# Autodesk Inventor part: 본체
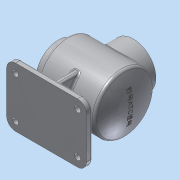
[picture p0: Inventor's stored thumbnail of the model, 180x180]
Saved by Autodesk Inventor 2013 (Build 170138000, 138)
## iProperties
Created: 2016-09
Part Number: 본체
Material: 알루미늄 6061
Document SubType Name: Modeling
Designer: dgall
Density: 2.71 g/cm^3
Mass: 972.437 g
Surface Area: 1283.14 cm^2
Volume: 358.833 cm^3
Author: dgall
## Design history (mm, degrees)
sketch "스케치1"
  geometry: L1 (-62, 0)-(60, 0); L2 (-62, 27)-(-47, 27); L3 (-47, 27)-(-47, 47); L4 (-47, 47)-(46.661, 47); L5 (-62, 27)-(-62, 38); L6 (-62, 38)-(-50, 38); L7 (-50, 38)-(-50, 50); L8 (-50, 50)-(48.562, 50); A1 r 115 centre (-55, 0) between (60, 0) and (48.562, 50); A2 r 112 centre (-55, 0) between (57, 0) and (46.661, 47); 2 further points
  constraints: 16 end point, 4 parallel, 4 point on circle, 3 perpendicular, 2 centre point, 2 point on line, 1 horizontal, 1 horizontal alignment, 1 midpoint
  dimensions: "d0" = 122 distance of L1.start L1.end; "d2" = 62 distance of L1.start point (0, 0); "d3" = 15 distance of L2.start L2.end; "d4" = 12 distance of L5.end L6.end; "d5" = 110 distance from line of L7 L1.end; "d6" = 76 diameter of L6 L1; "d7" = 54 diameter of L2 L1; "d8" = 100 diameter of L8 L1; "d9" = 94 diameter of L4 L1; "d10" = 230 diameter of A1; "d11" = 3 radial gap between concentric circles of A1 A2
revolve "회전1" sketch "스케치1" stored, may be unused: angle "d12" = 90 deg
sketch "스케치2" dims "d13" = 65
  geometry: C1 r 38 at (0, 0) reference; C2 r 27 at (0, 0) reference; 2 further points
  constraints: 2 vertical alignment, 1 coincident, 2 other
hole "구멍1" sketch "스케치2" at (0, 32.5) diameter "d15" = 3.242; stored, may be unused: countersink angle "d19" = 82 deg, drill point angle "d21" = 118 deg; dims "d16" = 8, "d17" = 3.023, "d18" = 2, "d20" = 10
node "작업 평면1"
sketch "스케치3" dims "d28" = 65
  geometry: C1 r 38 at (0, 0); C2 r 27 at (0, 0); 2 further points
  constraints: 2 centre point, 2 vertical alignment, 1 coincident, 2 other
  dimensions: "d26" = 76 diameter of C1; "d29" = 54 diameter of C2
extrude "돌출1" join sketch "스케치3" stored distance "d30" = 10; taper "d31" = 0 deg
extrude "돌출2" cut sketch "스케치3" distance "d32" = 61.5; taper "d33" = 0 deg
hole "구멍2" sketch "스케치3" diameter "d34" = 3.242; stored, may be unused: countersink angle "d38" = 82 deg, drill point angle "d40" = 118 deg; dims "d35" = 8, "d36" = 3.023, "d37" = 2, "d39" = 10
fillet "모깎기1" dims "d44" = 2
node "작업 평면2"
sketch "스케치4"
  geometry: L1 (67.5, 50)-(-67.5, 50); L2 (-67.5, 50)-(-67.5, -50); L3 (-67.5, -50)-(67.5, -50); L4 (67.5, -50)-(67.5, 50); 3 further points
  constraints: 8 end point, 2 midpoint, 2 parallel, 1 horizontal, 1 horizontal alignment, 1 perpendicular, 1 vertical alignment
  dimensions: "d46" = 135 distance of L2.end L3.end; "d48" = 100 distance of L3.end L1.start
extrude "돌출3" join sketch "스케치4" distance "d49" = 10; taper "d50" = 0 deg
fillet "모깎기2" dims "d51" = 15, "d52" = 5, "d53" = 3
sketch "스케치5"
  geometry: C1 r 5 at (-52.5, 35); C2 r 5 at (-52.5, -35); C3 r 5 at (52.5, -35); C4 r 5 at (52.5, 35); A1 r 15 centre (52.5, 35) between (67.5, 35) and (52.5, 50) reference; A2 r 15 centre (-52.5, 35) between (-52.5, 50) and (-67.5, 35) reference; A3 r 15 centre (-52.5, -35) between (-67.5, -35) and (-52.5, -50) reference; A4 r 15 centre (52.5, -35) between (52.5, -50) and (67.5, -35) reference; 1 further point
  constraints: 4 centre point, 4 coincident, 3 equal radius
  dimensions: "d54" = 10 diameter of C2
extrude "돌출4" cut sketch "스케치5" distance "d56" = 47.25; taper "d57" = 0 deg
sketch "스케치6"
  geometry: L1 (-72, 40)-(-72, 30) reference; L2 (-72, -30)-(-72, -40) reference; L3 (-72, 40)-(-72, 30) reference; L4 (-72, -30)-(-72, -40) reference; L5 (-72, -50)-(-72, -35) reference; L6 (-72, -35)-(-72, -50) reference; L7 (-72, -35)-(-72, 35) reference; L8 (-72, 50)-(-72, 35) reference; L9 (-72, 35)-(-72, 50) reference; L10 (-72, 35)-(-72, -35) reference; L11 (-30, 40)-(-72, 40); L12 (-30, -40)-(-72, -40); L13 (-72, 40)-(-72, -40); A1 r 50 centre (0, 0) between (-30, 40) and (-30, -40) reference; A2 r 50 centre (0, 0) between (-30, 40) and (-30, -40); 1 further point
  constraints: 6 end point, 4 point on circle, 3 perpendicular, 2 point on line, 1 centre point, 1 coincident, 1 concentric, 1 parallel
  dimensions: "d58" = 40 distance from line of point (0, 0) L12
extrude "돌출5" join sketch "스케치6" stored distance "d59" = 10; taper "d60" = 0 deg
sketch "스케치7"
  geometry: L1 (-45, -50)-(45.374, -50) reference; L2 (52.5, -72)-(-52.5, -72) reference; L3 (52.5, -72)-(67.5, -72) reference; L4 (67.5, -72)-(67.5, -82) reference; L5 (67.5, -82)-(52.5, -82) reference; L6 (52.5, -82)-(52.5, -72) reference; L7 (-67.5, -72)-(-52.5, -72) reference; L8 (-52.5, -72)-(-52.5, -82) reference; L9 (-52.5, -82)-(-67.5, -82) reference; L10 (-67.5, -82)-(-67.5, -72) reference; L11 (-40, -72)-(-37.988, -49); L12 (-37.988, -49)-(37.988, -49); L13 (37.988, -49)-(40, -72); L14 (-40, -72)-(40, -72); 3 further points
  constraints: 8 end point, 2 midpoint, 2 point on line, 2 vertical alignment, 1 equal length, 1 parallel, 1 perpendicular
  dimensions: "d61" = 95 deg angle of L3 L13; "d62" = 40 distance of L13.end point (0, -72); "d64" = 23 distance between parallel lines of L14 L12
extrude "돌출6" join sketch "스케치7" stored distance "d65" = 10; taper "d66" = 0 deg
fillet "모깎기3" dims "d67" = 3
fillet "모깎기4" dims "d68" = 3
chamfer "모따기1" distance "d69" = 1; stored, may be unused: second distance "d70" = 2, angle "d71" = 45 deg
node "작업 평면3"
sketch "스케치8"
  geometry: 2 further points
  constraints: 1 coincident, 1 other
feature "엠보싱1" sketch "스케치8" dims "d0" = 122, "d2" = 62, "d3" = 15, "d4" = 12, "d5" = 110, "d6" = 76, "d7" = 54, "d8" = 100, "d9" = 94, "d10" = 230, "d11" = 3, "d72" = 0.5, "d73" = 0
node "솔리드1"
pattern_circular "원형 패턴1" dims angle "d23" = 360 deg
pattern_circular "원형 패턴2" dims angle "d42" = 360 deg
node "투영된 루프1"
node "투영된 루프2"
node "투영된 루프3"
other parameters: "d25" = 65, "d45" = -147
